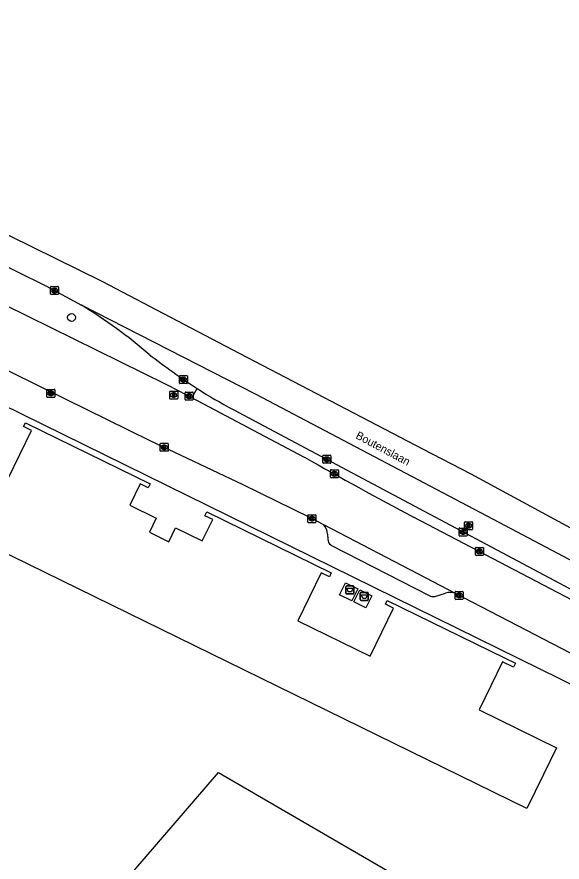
# Model space of a CAD drawing. Extents: x 160158 to 160921, y 381517 to 382041.
# Drawn here: x 160425.2 to 160493.3, y 381930.5 to 382036 of the extents above; entities that cross this region are included whole.
import ezdxf

# ---------------------------------------------------------------- set-up
doc = ezdxf.new("R2010")
doc.units = 0
for name, color, linetype in [('IMGEO_Afval_apart_plaats', 7, 'Continuous'), ('IMGEO_Boom', 7, 'Continuous'), ('IMGEO_Kolk', 7, 'Continuous'), ('IMGEO_Openbare_ruimte_label', 7, 'Continuous'), ('IMGEO_Pand', 7, 'Continuous'), ('IMGEO_Rijbaan_lokaal_open', 7, 'Continuous'), ('IMGEO_Rijbaan_regionaal_gesloten', 7, 'Continuous'), ('IMGEO_Rioolput', 7, 'Continuous'), ('IMGEO_Verkeerseiland_groen', 7, 'Continuous'), ('IMGEO_Voetpad_gesloten', 7, 'Continuous'), ('IMGEO_Voetpad_open', 7, 'Continuous')]:
    doc.layers.add(name, color=color, linetype=linetype)

msp = doc.modelspace()

# ---------------------------------------------------------------- linework, layer by layer
at = {"layer": 'IMGEO_Afval_apart_plaats'}
for p, q in [((160466.34, 381964.05), (160466.34, 381964.85)), ((160466.34, 381964.85), (160466.34, 381964.05)), ((160466.44, 381964.95), (160467.23, 381964.95)), ((160467.23, 381964.95), (160466.44, 381964.95)), ((160467.33, 381964.85), (160467.33, 381964.05)), ((160467.33, 381964.05), (160467.33, 381964.85)), ((160467.23, 381963.95), (160466.44, 381963.95)), ((160466.44, 381963.95), (160467.23, 381963.95)), ((160468.13, 381963.25), (160468.13, 381964.05)), ((160468.13, 381964.05), (160468.13, 381963.25)), ((160468.23, 381964.15), (160469.02, 381964.15)), ((160469.02, 381964.15), (160468.23, 381964.15)), ((160469.12, 381964.05), (160469.12, 381963.25)), ((160469.12, 381963.25), (160469.12, 381964.05)), ((160469.02, 381963.15), (160468.23, 381963.15)), ((160468.23, 381963.15), (160469.02, 381963.15))]:
    msp.add_line(p, q, dxfattribs=at)
for points in [[(160466.48, 381964.67), (160467.18, 381964.67), (160467.03, 381964.2), (160466.63, 381964.2), (160466.48, 381964.67)], [(160468.28, 381963.86), (160468.98, 381963.86), (160468.83, 381963.39), (160468.43, 381963.39), (160468.28, 381963.86)]]:
    msp.add_lwpolyline(points, dxfattribs=at)
for centre, start, end in [((160466.44, 381964.85), 90, 180), ((160466.44, 381964.85), 90, 180), ((160467.23, 381964.85), 0, 90), ((160467.23, 381964.85), 360, 90), ((160466.44, 381964.05), 180, 270), ((160466.44, 381964.05), 180, 270), ((160467.23, 381964.05), 270, 0), ((160467.23, 381964.05), 270, 0), ((160468.23, 381964.05), 90, 180), ((160468.23, 381964.05), 90, 180), ((160469.02, 381964.05), 0, 90), ((160469.02, 381964.05), 360, 90), ((160468.23, 381963.25), 180, 270), ((160468.23, 381963.25), 180, 270), ((160469.02, 381963.25), 270, 0), ((160469.02, 381963.25), 270, 0)]:
    msp.add_arc(centre, 0.1, start, end, dxfattribs=at)
at = {"layer": 'IMGEO_Boom'}
msp.add_circle((160432.05, 381998.47), 0.489, dxfattribs=at)
at = {"layer": 'IMGEO_Kolk'}
for p, q in [((160429.42, 382001.42), (160429.42, 382002.27)), ((160429.49, 382002.35), (160430.35, 382002.35)), ((160429.91, 382002.12), (160429.93, 382002.12)), ((160430.42, 382002.27), (160430.42, 382001.42)), ((160430.35, 382001.34), (160429.49, 382001.34)), ((160429.93, 382001.57), (160429.9, 382001.57)), ((160445.6, 381991.22), (160446.45, 381991.22)), ((160445.52, 381990.29), (160445.52, 381991.15)), ((160446.45, 381990.22), (160445.6, 381990.22)), ((160446.01, 381991), (160446.04, 381991)), ((160446.03, 381990.44), (160446.01, 381990.44)), ((160446.52, 381991.15), (160446.52, 381990.29)), ((160428.97, 381988.58), (160428.97, 381989.43)), ((160429.04, 381989.5), (160429.89, 381989.5)), ((160429.45, 381989.28), (160429.48, 381989.28)), ((160429.97, 381989.43), (160429.97, 381988.58)), ((160446.23, 381988.22), (160446.23, 381989.08)), ((160446.31, 381989.15), (160447.16, 381989.15)), ((160447.24, 381989.08), (160447.24, 381988.22)), ((160429.89, 381988.5), (160429.04, 381988.5)), ((160429.48, 381988.72), (160429.45, 381988.72)), ((160447.16, 381988.15), (160446.31, 381988.15)), ((160446.72, 381988.93), (160446.75, 381988.93)), ((160446.74, 381988.37), (160446.72, 381988.37)), ((160443.21, 381982.76), (160444.06, 381982.76)), ((160443.14, 381981.83), (160443.14, 381982.68)), ((160444.06, 381981.76), (160443.21, 381981.76)), ((160443.62, 381982.54), (160443.65, 381982.54)), ((160443.65, 381981.98), (160443.62, 381981.98)), ((160444.14, 381982.68), (160444.14, 381981.83)), ((160463.45, 381980.35), (160463.45, 381981.2)), ((160463.53, 381981.27), (160464.38, 381981.27)), ((160463.94, 381981.05), (160463.97, 381981.05)), ((160464.46, 381981.2), (160464.46, 381980.35)), ((160464.38, 381980.27), (160463.53, 381980.27)), ((160463.96, 381980.49), (160463.94, 381980.49)), ((160464.4, 381978.53), (160464.4, 381979.38)), ((160464.47, 381979.46), (160465.32, 381979.46)), ((160464.88, 381979.23), (160464.91, 381979.23)), ((160464.91, 381978.68), (160464.88, 381978.68)), ((160465.4, 381979.38), (160465.4, 381978.53)), ((160465.32, 381978.45), (160464.47, 381978.45)), ((160461.59, 381972.92), (160461.59, 381973.78)), ((160461.66, 381973.85), (160462.52, 381973.85)), ((160462.08, 381973.63), (160462.1, 381973.63)), ((160462.59, 381973.78), (160462.59, 381972.92)), ((160462.52, 381972.85), (160461.66, 381972.85)), ((160462.1, 381973.07), (160462.07, 381973.07)), ((160480.54, 381972.18), (160481.4, 381972.18)), ((160480.47, 381971.26), (160480.47, 381972.11)), ((160481.4, 381971.18), (160480.54, 381971.18)), ((160480.98, 381971.4), (160480.95, 381971.4)), ((160480.96, 381971.96), (160480.98, 381971.96)), ((160481.47, 381972.11), (160481.47, 381971.26)), ((160482.51, 381968.83), (160482.51, 381969.69)), ((160482.59, 381969.76), (160483.44, 381969.76)), ((160483, 381969.54), (160483.03, 381969.54)), ((160483.51, 381969.69), (160483.51, 381968.83)), ((160483.44, 381968.76), (160482.59, 381968.76)), ((160483.02, 381968.98), (160483, 381968.98)), ((160479.97, 381963.34), (160479.97, 381964.19)), ((160480.05, 381964.27), (160480.9, 381964.27)), ((160480.46, 381964.05), (160480.49, 381964.05)), ((160480.98, 381964.19), (160480.98, 381963.34)), ((160480.9, 381963.27), (160480.05, 381963.27)), ((160480.48, 381963.49), (160480.46, 381963.49))]:
    msp.add_line(p, q, dxfattribs=at)
for points in [[(160429.42, 382001.42), (160429.42, 382002.27)], [(160429.49, 382002.35), (160430.35, 382002.35)], [(160429.74, 382002.04), (160429.86, 382002.04), (160429.86, 382001.89), (160429.99, 382002.04), (160430.16, 382002.04), (160430.01, 382001.89), (160430.16, 382001.64), (160430.01, 382001.64), (160429.93, 382001.81), (160429.86, 382001.74), (160429.86, 382001.64), (160429.74, 382001.64), (160429.74, 382002.04)], [(160430.42, 382002.27), (160430.42, 382001.42)], [(160430.35, 382001.34), (160429.49, 382001.34)], [(160445.6, 381991.22), (160446.45, 381991.22)], [(160445.52, 381990.29), (160445.52, 381991.15)], [(160446.45, 381990.22), (160445.6, 381990.22)], [(160445.84, 381990.92), (160445.97, 381990.92), (160445.97, 381990.77), (160446.1, 381990.92), (160446.26, 381990.92), (160446.12, 381990.77), (160446.27, 381990.52), (160446.12, 381990.52), (160446.03, 381990.68), (160445.97, 381990.62), (160445.97, 381990.52), (160445.84, 381990.52), (160445.84, 381990.92)], [(160446.52, 381991.15), (160446.52, 381990.29)], [(160428.97, 381988.58), (160428.97, 381989.43)], [(160429.04, 381989.5), (160429.89, 381989.5)], [(160429.29, 381989.2), (160429.41, 381989.2), (160429.41, 381989.05), (160429.54, 381989.2), (160429.7, 381989.2), (160429.56, 381989.05), (160429.71, 381988.8), (160429.56, 381988.8), (160429.47, 381988.97), (160429.41, 381988.9), (160429.41, 381988.8), (160429.29, 381988.8), (160429.29, 381989.2)], [(160429.97, 381989.43), (160429.97, 381988.58)], [(160446.23, 381988.22), (160446.23, 381989.08)], [(160446.31, 381989.15), (160447.16, 381989.15)], [(160447.24, 381989.08), (160447.24, 381988.22)], [(160429.89, 381988.5), (160429.04, 381988.5)], [(160447.16, 381988.15), (160446.31, 381988.15)], [(160446.55, 381988.85), (160446.68, 381988.85), (160446.68, 381988.7), (160446.81, 381988.85), (160446.97, 381988.85), (160446.83, 381988.7), (160446.98, 381988.45), (160446.83, 381988.45), (160446.74, 381988.62), (160446.68, 381988.55), (160446.68, 381988.45), (160446.55, 381988.45), (160446.55, 381988.85)], [(160443.21, 381982.76), (160444.06, 381982.76)], [(160443.14, 381981.83), (160443.14, 381982.68)], [(160444.06, 381981.76), (160443.21, 381981.76)], [(160443.46, 381982.46), (160443.58, 381982.46), (160443.58, 381982.3), (160443.71, 381982.46), (160443.87, 381982.46), (160443.73, 381982.31), (160443.88, 381982.06), (160443.73, 381982.06), (160443.64, 381982.22), (160443.58, 381982.15), (160443.58, 381982.06), (160443.46, 381982.06), (160443.46, 381982.46)], [(160444.14, 381982.68), (160444.14, 381981.83)], [(160463.45, 381980.35), (160463.45, 381981.2)], [(160463.53, 381981.27), (160464.38, 381981.27)], [(160463.77, 381980.97), (160463.9, 381980.97), (160463.9, 381980.82), (160464.03, 381980.97), (160464.19, 381980.97), (160464.05, 381980.82), (160464.2, 381980.57), (160464.05, 381980.57), (160463.96, 381980.74), (160463.9, 381980.67), (160463.9, 381980.57), (160463.77, 381980.57), (160463.77, 381980.97)], [(160464.46, 381981.2), (160464.46, 381980.35)], [(160464.38, 381980.27), (160463.53, 381980.27)], [(160464.4, 381978.53), (160464.4, 381979.38)], [(160464.47, 381979.46), (160465.32, 381979.46)], [(160464.72, 381979.15), (160464.84, 381979.15), (160464.84, 381979), (160464.97, 381979.15), (160465.13, 381979.15), (160464.99, 381979), (160465.14, 381978.75), (160464.99, 381978.75), (160464.9, 381978.92), (160464.84, 381978.85), (160464.84, 381978.75), (160464.72, 381978.75), (160464.72, 381979.15)], [(160465.4, 381979.38), (160465.4, 381978.53)], [(160465.32, 381978.45), (160464.47, 381978.45)], [(160461.59, 381972.92), (160461.59, 381973.78)], [(160461.66, 381973.85), (160462.52, 381973.85)], [(160461.91, 381973.55), (160462.03, 381973.55), (160462.03, 381973.4), (160462.16, 381973.55), (160462.33, 381973.55), (160462.18, 381973.4), (160462.33, 381973.15), (160462.18, 381973.15), (160462.1, 381973.32), (160462.03, 381973.25), (160462.03, 381973.15), (160461.91, 381973.15), (160461.91, 381973.55)], [(160462.59, 381973.78), (160462.59, 381972.92)], [(160462.52, 381972.85), (160461.66, 381972.85)], [(160480.54, 381972.18), (160481.4, 381972.18)], [(160480.47, 381971.26), (160480.47, 381972.11)], [(160481.4, 381971.18), (160480.54, 381971.18)], [(160480.79, 381971.88), (160480.91, 381971.88), (160480.91, 381971.73), (160481.04, 381971.88), (160481.21, 381971.88), (160481.06, 381971.73), (160481.21, 381971.48), (160481.06, 381971.48), (160480.98, 381971.65), (160480.91, 381971.58), (160480.91, 381971.48), (160480.79, 381971.48), (160480.79, 381971.88)], [(160481.47, 381972.11), (160481.47, 381971.26)], [(160482.51, 381968.83), (160482.51, 381969.69)], [(160482.59, 381969.76), (160483.44, 381969.76)], [(160482.83, 381969.46), (160482.96, 381969.46), (160482.96, 381969.31), (160483.09, 381969.46), (160483.25, 381969.46), (160483.1, 381969.31), (160483.26, 381969.06), (160483.1, 381969.06), (160483.02, 381969.22), (160482.96, 381969.16), (160482.96, 381969.06), (160482.83, 381969.06), (160482.83, 381969.46)], [(160483.51, 381969.69), (160483.51, 381968.83)], [(160483.44, 381968.76), (160482.59, 381968.76)], [(160479.97, 381963.34), (160479.97, 381964.19)], [(160480.05, 381964.27), (160480.9, 381964.27)], [(160480.29, 381963.97), (160480.42, 381963.97), (160480.42, 381963.82), (160480.55, 381963.97), (160480.71, 381963.97), (160480.57, 381963.82), (160480.72, 381963.57), (160480.57, 381963.57), (160480.48, 381963.73), (160480.42, 381963.67), (160480.42, 381963.57), (160480.29, 381963.57), (160480.29, 381963.97)], [(160480.98, 381964.19), (160480.98, 381963.34)], [(160480.9, 381963.27), (160480.05, 381963.27)]]:
    msp.add_lwpolyline(points, dxfattribs=at)
for centre, start, end in [((160429.5, 382002.27), 91.552, 178.448), ((160429.5, 382002.27), 91.552, 178.448), ((160430.34, 382002.27), 1.552, 88.448), ((160430.34, 382002.27), 1.552, 88.448), ((160429.5, 382001.42), 181.552, 268.448), ((160429.5, 382001.42), 181.552, 268.448), ((160430.34, 382001.42), 271.552, 358.448), ((160430.34, 382001.42), 271.552, 358.448), ((160445.6, 381991.14), 91.552, 178.448), ((160445.6, 381991.14), 91.552, 178.448), ((160446.45, 381991.14), 1.552, 88.448), ((160446.45, 381991.14), 1.552, 88.448), ((160445.6, 381990.3), 181.552, 268.448), ((160445.6, 381990.3), 181.552, 268.448), ((160446.45, 381990.3), 271.552, 358.448), ((160446.45, 381990.3), 271.552, 358.448), ((160429.04, 381989.43), 91.552, 178.448), ((160429.04, 381989.43), 91.552, 178.448), ((160429.89, 381989.43), 1.552, 88.448), ((160429.89, 381989.43), 1.552, 88.448), ((160446.31, 381989.08), 91.552, 178.448), ((160446.31, 381989.08), 91.552, 178.448), ((160447.16, 381989.08), 1.552, 88.448), ((160447.16, 381989.08), 1.552, 88.448), ((160429.04, 381988.58), 181.552, 268.448), ((160429.04, 381988.58), 181.552, 268.448), ((160429.89, 381988.58), 271.552, 358.448), ((160429.89, 381988.58), 271.552, 358.448), ((160446.31, 381988.23), 181.552, 268.448), ((160446.31, 381988.23), 181.552, 268.448), ((160447.16, 381988.23), 271.552, 358.448), ((160447.16, 381988.23), 271.552, 358.448), ((160443.21, 381982.68), 91.552, 178.448), ((160443.21, 381982.68), 91.552, 178.448), ((160444.06, 381982.68), 1.552, 88.448), ((160444.06, 381982.68), 1.552, 88.448), ((160443.21, 381981.83), 181.552, 268.448), ((160443.21, 381981.83), 181.552, 268.448), ((160444.06, 381981.83), 271.552, 358.448), ((160444.06, 381981.83), 271.552, 358.448), ((160463.53, 381981.2), 91.552, 178.448), ((160463.53, 381981.2), 91.552, 178.448), ((160464.38, 381981.2), 1.552, 88.448), ((160464.38, 381981.2), 1.552, 88.448), ((160463.53, 381980.35), 181.552, 268.448), ((160463.53, 381980.35), 181.552, 268.448), ((160464.38, 381980.35), 271.552, 358.448), ((160464.38, 381980.35), 271.552, 358.448), ((160464.47, 381979.38), 91.552, 178.448), ((160464.47, 381979.38), 91.552, 178.448), ((160464.47, 381978.53), 181.552, 268.448), ((160464.47, 381978.53), 181.552, 268.448), ((160465.32, 381979.38), 1.552, 88.448), ((160465.32, 381979.38), 1.552, 88.448), ((160465.32, 381978.53), 271.552, 358.448), ((160465.32, 381978.53), 271.552, 358.448), ((160461.66, 381973.78), 91.552, 178.448), ((160461.66, 381973.78), 91.552, 178.448), ((160462.51, 381973.78), 1.552, 88.448), ((160462.51, 381973.78), 1.552, 88.448), ((160461.66, 381972.93), 181.552, 268.448), ((160461.66, 381972.93), 181.552, 268.448), ((160462.51, 381972.93), 271.552, 358.448), ((160462.51, 381972.93), 271.552, 358.448), ((160480.55, 381972.11), 91.552, 178.448), ((160480.55, 381972.11), 91.552, 178.448), ((160481.39, 381972.11), 1.552, 88.448), ((160481.39, 381972.11), 1.552, 88.448), ((160480.55, 381971.26), 181.552, 268.448), ((160480.55, 381971.26), 181.552, 268.448), ((160481.39, 381971.26), 271.552, 358.448), ((160481.39, 381971.26), 271.552, 358.448), ((160482.59, 381969.68), 91.552, 178.448), ((160482.59, 381969.68), 91.552, 178.448), ((160483.44, 381969.68), 1.552, 88.448), ((160483.44, 381969.68), 1.552, 88.448), ((160482.59, 381968.84), 181.552, 268.448), ((160482.59, 381968.84), 181.552, 268.448), ((160483.44, 381968.84), 271.552, 358.448), ((160483.44, 381968.84), 271.552, 358.448), ((160480.05, 381964.19), 91.552, 178.448), ((160480.05, 381964.19), 91.552, 178.448), ((160480.9, 381964.19), 1.552, 88.448), ((160480.9, 381964.19), 1.552, 88.448), ((160480.05, 381963.34), 181.552, 268.448), ((160480.05, 381963.34), 181.552, 268.448), ((160480.9, 381963.34), 271.552, 358.448), ((160480.9, 381963.34), 271.552, 358.448)]:
    msp.add_arc(centre, 0.0765, start, end, dxfattribs=at)
for centre, major_axis, ratio, start_param, end_param in [((160429.91, 382001.84), (-0.387, 0.002), 0.722429, 4.712389, 7.853982), ((160429.93, 382001.84), (-0.39, 0.002), 0.717154, 1.570796, 4.712389), ((160446.01, 381990.72), (-0.387, 0.002), 0.722429, 4.712389, 7.853982), ((160446.03, 381990.72), (-0.39, 0.002), 0.717154, 1.570796, 4.712389), ((160429.45, 381989), (-0.387, 0.002), 0.722429, 4.712389, 7.853982), ((160429.48, 381989), (-0.39, 0.002), 0.717154, 1.570796, 4.712389), ((160446.72, 381988.65), (-0.387, 0.002), 0.722429, 4.712389, 7.853982), ((160446.75, 381988.65), (-0.39, 0.002), 0.717154, 1.570796, 4.712389), ((160443.62, 381982.26), (-0.387, 0.002), 0.722429, 4.712389, 7.853982), ((160443.65, 381982.26), (-0.39, 0.002), 0.717154, 1.570796, 4.712389), ((160463.94, 381980.77), (-0.387, 0.002), 0.722429, 4.712389, 7.853982), ((160463.97, 381980.77), (-0.39, 0.002), 0.717154, 1.570796, 4.712389), ((160464.88, 381978.95), (-0.387, 0.002), 0.722429, 4.712389, 7.853982), ((160464.91, 381978.95), (-0.39, 0.002), 0.717154, 1.570796, 4.712389), ((160462.08, 381973.35), (-0.387, 0.002), 0.722429, 4.712389, 7.853982), ((160462.1, 381973.35), (-0.39, 0.002), 0.717154, 1.570796, 4.712389), ((160480.96, 381971.68), (-0.387, 0.002), 0.722429, 4.712389, 7.853982), ((160480.98, 381971.68), (-0.39, 0.002), 0.717154, 1.570796, 4.712389), ((160483, 381969.26), (-0.387, 0.002), 0.722429, 4.712389, 7.853982), ((160483.02, 381969.26), (-0.39, 0.002), 0.717154, 1.570796, 4.712389), ((160480.46, 381963.77), (-0.387, 0.002), 0.722429, 4.712389, 7.853982), ((160480.49, 381963.77), (-0.39, 0.002), 0.717154, 1.570796, 4.712389)]:
    msp.add_ellipse(centre, major_axis=major_axis, ratio=ratio, start_param=start_param, end_param=end_param, dxfattribs=at)
at = {"layer": 'IMGEO_Pand'}
for points in [[(160424.12, 381978.38), (160427.05, 381984.35), (160426.04, 381984.84), (160426.28, 381985.32), (160441.86, 381977.69), (160441.62, 381977.2), (160440.61, 381977.7), (160439.34, 381975.03), (160442.64, 381973.4), (160441.78, 381971.68), (160443.62, 381970.76), (160444.21, 381970.47), (160445.04, 381972.2), (160448.35, 381970.59), (160449.69, 381973.24), (160448.72, 381973.72), (160448.96, 381974.21), (160464.5, 381966.57), (160464.27, 381966.09), (160463.25, 381966.59), (160460.31, 381960.6), (160469.35, 381956.16), (160472.28, 381962.16), (160471.27, 381962.66), (160471.5, 381963.14), (160486.13, 381955.98), (160487.52, 381955.3), (160487.29, 381954.82), (160485.9, 381955.49), (160482.96, 381949.48), (160492.63, 381944.75), (160491.01, 381941.42), (160488.92, 381937.14), (160420.36, 381970.72)], [(160437.51, 381926.21), (160437.24, 381926.36), (160450.4, 381941.66), (160481.51, 381923.6), (160482.58, 381922.97), (160477.83, 381914.8), (160470.36, 381919.14), (160465.11, 381910.14), (160437.51, 381926.21)]]:
    msp.add_lwpolyline(points, dxfattribs=at)
at = {"layer": 'IMGEO_Rijbaan_lokaal_open'}
for points in [[(160447.08, 381988.46), (160445.48, 381989.29), (160443.87, 381990.12), (160423.76, 382000), (160407.84, 382007.82)], [(160463.58, 381972.57), (160461.9, 381973.44), (160453.49, 381977.59), (160441.88, 381983.09), (160428.58, 381989.59), (160413.94, 381996.85), (160407.39, 382000), (160404.8, 382001.25), (160399.86, 382003.52)], [(160461.16, 381981.01), (160447.08, 381988.46)], [(160522.99, 381948.07), (160522.19, 381948.7), (160500, 381960.33), (160474.79, 381973.54)], [(160479.96, 381964.05), (160476.35, 381965.93), (160463.58, 381972.57)], [(160515.07, 381945.82), (160500, 381953.65), (160479.96, 381964.05)]]:
    msp.add_lwpolyline(points, dxfattribs=at)
msp.add_arc((160725.43, 382446.7), 535.44, 240.4265, 242.0895, dxfattribs=at)
at = {"layer": 'IMGEO_Rijbaan_regionaal_gesloten'}
for points in [[(160365.18, 382036.01), (160365.33, 382035.94), (160367.45, 382035.01), (160371.7, 382033.18), (160373.84, 382032.28), (160378.36, 382030.28), (160388.19, 382025.93), (160410.06, 382015.8), (160421.33, 382010.11), (160435.82, 382003.01), (160452.11, 381994.48), (160475.91, 381982.09), (160481.94, 381978.95), (160497.3, 381970.61), (160502.02, 381968.05), (160530.99, 381953.18), (160555.81, 381940.96), (160581.54, 381928.32), (160591.89, 381923.24), (160619.54, 381909.79), (160639.9, 381900.07)], [(160413.3, 382010.08), (160428.84, 382002.41), (160433.28, 382000)], [(160582.11, 381924.04), (160540.32, 381944.76), (160514.36, 381957.64), (160495.71, 381967.48), (160485.49, 381972.87), (160455.13, 381988.87), (160433.28, 382000)], [(160452.24, 381986.98), (160494.28, 381964.62), (160500, 381961.58), (160502.84, 381960.06), (160513.24, 381954.71), (160523.65, 381949.34)]]:
    msp.add_lwpolyline(points, dxfattribs=at)
for centre, radius, start, end in [((160401.91, 381947.85), 60.86, 49.091, 58.9748), ((160503.18, 382073.97), 100.95, 232.5298, 236.6877), ((160482.41, 382043.93), 64.45, 237.452, 242.0842)]:
    msp.add_arc(centre, radius, start, end, dxfattribs=at)
at = {"layer": 'IMGEO_Rioolput'}
for p, q in [((160444.31, 381988.36), (160444.31, 381989.22)), ((160444.38, 381989.29), (160445.24, 381989.29)), ((160444.8, 381989.07), (160444.82, 381989.07)), ((160445.31, 381989.22), (160445.31, 381988.36)), ((160445.24, 381988.29), (160444.38, 381988.29)), ((160444.82, 381988.51), (160444.8, 381988.51)), ((160481.16, 381972.04), (160481.16, 381972.89)), ((160481.23, 381972.97), (160482.08, 381972.97)), ((160481.64, 381972.75), (160481.67, 381972.75)), ((160481.67, 381972.19), (160481.64, 381972.19)), ((160482.16, 381972.89), (160482.16, 381972.04)), ((160482.08, 381971.97), (160481.23, 381971.97))]:
    msp.add_line(p, q, dxfattribs=at)
for points in [[(160444.31, 381988.36), (160444.31, 381989.22)], [(160444.38, 381989.29), (160445.24, 381989.29)], [(160445.31, 381989.22), (160445.31, 381988.36)], [(160445.24, 381988.29), (160444.38, 381988.29)], [(160444.9, 381988.99), (160444.65, 381988.99), (160444.65, 381988.59)], [(160444.65, 381988.59), (160444.77, 381988.59), (160444.77, 381988.75), (160444.78, 381988.75)], [(160444.83, 381988.91), (160444.77, 381988.91), (160444.77, 381988.83)], [(160444.77, 381988.83), (160444.82, 381988.83)], [(160444.83, 381988.72), (160444.9, 381988.59), (160445.04, 381988.59), (160444.97, 381988.72)], [(160481.16, 381972.04), (160481.16, 381972.89)], [(160481.23, 381972.97), (160482.08, 381972.97)], [(160481.74, 381972.66), (160481.49, 381972.67), (160481.49, 381972.27)], [(160481.49, 381972.27), (160481.62, 381972.27), (160481.62, 381972.43), (160481.63, 381972.43)], [(160481.67, 381972.59), (160481.62, 381972.59), (160481.62, 381972.5)], [(160481.62, 381972.5), (160481.67, 381972.5)], [(160481.67, 381972.4), (160481.75, 381972.27), (160481.88, 381972.27), (160481.82, 381972.39)], [(160482.16, 381972.89), (160482.16, 381972.04)], [(160482.08, 381971.97), (160481.23, 381971.97)]]:
    msp.add_lwpolyline(points, dxfattribs=at)
for centre, radius, start, end in [((160444.39, 381989.21), 0.0765, 91.552, 178.448), ((160444.39, 381989.21), 0.0765, 91.552, 178.448), ((160445.23, 381989.21), 0.0765, 1.552, 88.448), ((160445.23, 381989.21), 0.0765, 1.552, 88.448), ((160444.39, 381988.37), 0.0765, 181.552, 268.448), ((160444.39, 381988.37), 0.0765, 181.552, 268.448), ((160444.78, 381988.7), 0.0533, 26.0293, 88.6989), ((160444.81, 381989.02), 0.19, 274.7715, 282.9687), ((160444.83, 381988.81), 0.0964, 77.0061, 93.1865), ((160444.85, 381988.87), 0.0378, 276.6634, 79.6772), ((160444.9, 381988.88), 0.109, 350.3612, 89.416), ((160444.9, 381988.88), 0.112, 277.5842, 350.9817), ((160444.88, 381988.66), 0.108, 29.5134, 73.7905), ((160445.23, 381988.37), 0.0765, 271.552, 358.448), ((160445.23, 381988.37), 0.0765, 271.552, 358.448), ((160481.23, 381972.89), 0.0765, 91.552, 178.448), ((160481.23, 381972.89), 0.0765, 91.552, 178.448), ((160481.63, 381972.38), 0.0533, 26.0293, 88.6989), ((160481.68, 381972.49), 0.0964, 77.0061, 93.1865), ((160481.65, 381972.69), 0.19, 274.7715, 282.9687), ((160481.69, 381972.55), 0.0378, 276.6634, 79.6772), ((160481.74, 381972.55), 0.109, 350.3612, 89.416), ((160481.74, 381972.55), 0.112, 277.5842, 350.9817), ((160481.73, 381972.34), 0.108, 29.5134, 73.7905), ((160482.08, 381972.89), 0.0765, 1.552, 88.448), ((160482.08, 381972.89), 0.0765, 1.552, 88.448), ((160481.23, 381972.04), 0.0765, 181.552, 268.448), ((160481.23, 381972.04), 0.0765, 181.552, 268.448), ((160482.08, 381972.04), 0.0765, 271.552, 358.448), ((160482.08, 381972.04), 0.0765, 271.552, 358.448)]:
    msp.add_arc(centre, radius, start, end, dxfattribs=at)
for centre, major_axis, ratio, start_param, end_param in [((160444.8, 381988.79), (-0.387, 0.002), 0.722429, 4.712389, 7.853982), ((160444.82, 381988.79), (-0.39, 0.002), 0.717154, 1.570796, 4.712389), ((160481.64, 381972.47), (-0.387, 0.002), 0.722429, 4.712389, 7.853982), ((160481.67, 381972.47), (-0.39, 0.002), 0.717154, 1.570796, 4.712389)]:
    msp.add_ellipse(centre, major_axis=major_axis, ratio=ratio, start_param=start_param, end_param=end_param, dxfattribs=at)
at = {"layer": 'IMGEO_Verkeerseiland_groen'}
msp.add_lwpolyline([(160447.08, 381988.46), (160447.74, 381989.6)], dxfattribs=at)
at = {"layer": 'IMGEO_Voetpad_gesloten'}
for points in [[(160465.54, 381963.83), (160466.28, 381965.35), (160467.8, 381964.6), (160467.05, 381963.08), (160465.54, 381963.83)], [(160468.05, 381964.48), (160469.57, 381963.73), (160468.82, 381962.22), (160467.3, 381962.96), (160468.05, 381964.48)]]:
    msp.add_lwpolyline(points, dxfattribs=at)
at = {"layer": 'IMGEO_Voetpad_open'}
for points in [[(160374, 382010.92), (160378.89, 382008.88), (160397.93, 382000), (160402.45, 381997.89), (160498.28, 381950.8)], [(160464.03, 381971.42), (160464.06, 381970.78)], [(160464.46, 381970.06), (160476.72, 381963.76)], [(160477.43, 381963.64), (160478.79, 381964.05)]]:
    msp.add_lwpolyline(points, dxfattribs=at)
for centre, radius, start, end in [((160461.86, 381971.24), 2.18, 4.9296, 37.615), ((160464.92, 381970.79), 0.858, 180.9473, 237.8293), ((160477.27, 381964.93), 1.3, 244.7044, 276.8437), ((160479.36, 381962.03), 2.11, 73.5405, 105.9723)]:
    msp.add_arc(centre, radius, start, end, dxfattribs=at)

# ---------------------------------------------------------------- texts
at = {"layer": 'IMGEO_Openbare_ruimte_label'}
msp.add_text('Boutenslaan', height=1, rotation=331.9747, dxfattribs=at).set_placement((160467.46, 381983.43))

doc.saveas('drawing.dxf')
